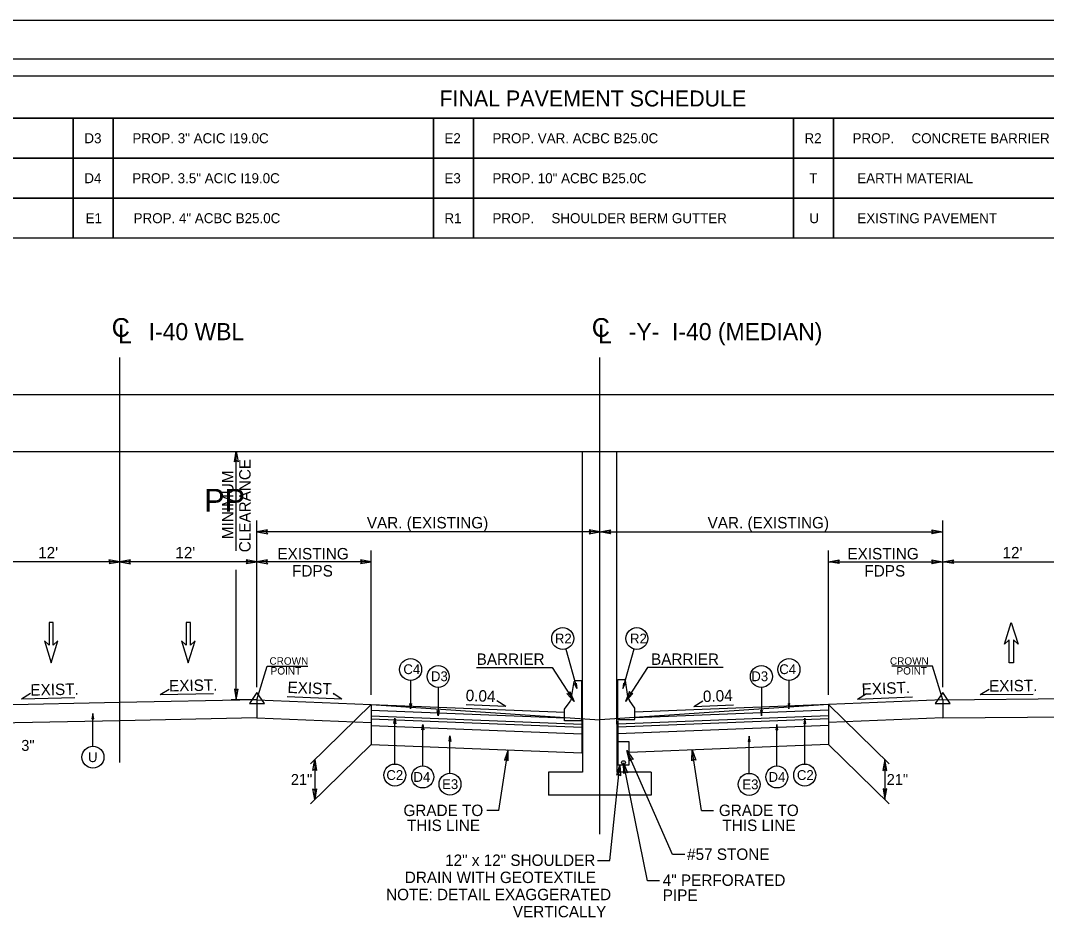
# Model space of a CAD drawing. Extents: x 1553884 to 1554215, y 810431 to 810779.
# Drawn here: x 1553971.2 to 1554061, y 810517.4 to 810596 of the extents above; entities that cross this region are included whole.
import ezdxf

# ---------------------------------------------------------------- set-up
doc = ezdxf.new("R2010")
doc.units = 0
for name, color, linetype in [('Old_Level_15', 7, 'Continuous'), ('Old_Level_2', 7, 'Continuous'), ('Old_Level_20', 7, 'Continuous'), ('P_RDY_Bridge_Abutment', 7, 'Continuous'), ('Prop Dimension', 7, 'Continuous'), ('Prop Hatching', 7, 'Continuous'), ('Prop Lane Arrow CELL', 7, 'Continuous'), ('Prop Shade Light', 7, 'Continuous'), ('Sheet Sticker Exception Certification CELL', 7, 'Continuous'), ('Typical Arrow Superelevation CELL', 7, 'Continuous'), ('Typical Detail Pavement Repair CELL', 7, 'Continuous'), ('Typical Median Barrier CELL', 7, 'Continuous'), ('Typical Shoulder Slope CELL', 7, 'Continuous'), ('Typical Text Centerline CELL', 7, 'Continuous'), ('Typical Text ID Circle CELL', 7, 'Continuous')]:
    doc.layers.add(name, color=color, linetype=linetype)

msp = doc.modelspace()

# ---------------------------------------------------------------- linework, layer by layer
at = {"layer": 'Old_Level_15'}
for points in [[(1553989.916, 810557.319), (1553990.078, 810558.257), (1553990.244, 810557.314), (1553990.078, 810557.434)], [(1553992.825, 810551.347), (1553991.887, 810551.186), (1553992.83, 810551.019), (1553992.71, 810551.186)], [(1554020.95, 810551.024), (1554021.887, 810551.186), (1554020.945, 810551.352), (1554021.064, 810551.186)], [(1554022.825, 810551.024), (1554021.887, 810551.186), (1554022.83, 810551.352), (1554022.71, 810551.186)], [(1554050.95, 810551.347), (1554051.887, 810551.186), (1554050.945, 810551.019), (1554051.064, 810551.186)], [(1553978.95, 810548.4), (1553979.887, 810548.561), (1553978.945, 810548.728), (1553979.064, 810548.561)], [(1553980.825, 810548.722), (1553979.887, 810548.561), (1553980.83, 810548.394), (1553980.71, 810548.561)], [(1553990.95, 810548.4), (1553991.887, 810548.561), (1553990.945, 810548.728), (1553991.064, 810548.561)], [(1553992.825, 810548.722), (1553991.887, 810548.561), (1553992.83, 810548.394), (1553992.71, 810548.561)], [(1554000.95, 810548.4), (1554001.887, 810548.561), (1554000.945, 810548.728), (1554001.064, 810548.561)], [(1554042.825, 810548.4), (1554041.887, 810548.561), (1554042.83, 810548.728), (1554042.71, 810548.561)], [(1554050.95, 810548.722), (1554051.887, 810548.561), (1554050.945, 810548.394), (1554051.064, 810548.561)], [(1554052.825, 810548.4), (1554051.887, 810548.561), (1554052.83, 810548.728), (1554052.71, 810548.561)], [(1553989.916, 810537.411), (1553990.078, 810536.474), (1553990.244, 810537.416), (1553990.078, 810537.296)], [(1554019.278, 810537.197), (1554019.654, 810536.323), (1554019, 810537.022), (1554019.205, 810537.013)], [(1554019.829, 810537.949), (1554019.878, 810537.476), (1554019.67, 810537.907), (1554019.766, 810537.872)], [(1554023.946, 810537.949), (1554023.897, 810537.476), (1554024.105, 810537.907), (1554024.008, 810537.872)], [(1554024.497, 810537.197), (1554024.121, 810536.323), (1554024.774, 810537.022), (1554024.569, 810537.013)], [(1553977.623, 810534.818), (1553977.542, 810535.287), (1553977.459, 810534.815), (1553977.542, 810534.875)], [(1554005.417, 810536.156), (1554005.336, 810535.688), (1554005.253, 810536.159), (1554005.336, 810536.099)], [(1554007.829, 810535.539), (1554007.748, 810535.07), (1554007.665, 810535.541), (1554007.748, 810535.481)], [(1554035.946, 810535.539), (1554036.027, 810535.07), (1554036.11, 810535.541), (1554036.027, 810535.481)], [(1554038.358, 810536.156), (1554038.439, 810535.688), (1554038.522, 810536.159), (1554038.439, 810536.099)], [(1554003.876, 810534.391), (1554003.957, 810534.86), (1554004.04, 810534.389), (1554003.957, 810534.449)], [(1554039.898, 810534.391), (1554039.817, 810534.86), (1554039.734, 810534.389), (1554039.817, 810534.449)], [(1554006.317, 810533.856), (1554006.397, 810534.325), (1554006.481, 810533.853), (1554006.397, 810533.913)], [(1554037.458, 810533.856), (1554037.377, 810534.325), (1554037.294, 810533.853), (1554037.377, 810533.913)], [(1554008.7, 810532.846), (1554008.781, 810533.315), (1554008.864, 810532.843), (1554008.781, 810532.903)], [(1554035.038, 810532.827), (1554034.957, 810533.296), (1554034.874, 810532.825), (1554034.957, 810532.885)], [(1554013.876, 810531.144), (1554013.857, 810532.095), (1554013.551, 810531.188), (1554013.733, 810531.281)], [(1554024.491, 810531.127), (1554024.255, 810532.048), (1554024.793, 810531.256), (1554024.592, 810531.297)], [(1554029.951, 810531.146), (1554029.969, 810532.097), (1554030.276, 810531.19), (1554030.093, 810531.284)], [(1553996.787, 810530.304), (1553996.948, 810531.242), (1553997.115, 810530.299), (1553996.948, 810530.419)], [(1554023.988, 810530.022), (1554023.961, 810530.973), (1554024.311, 810530.082), (1554024.124, 810530.166)], [(1554046.988, 810530.304), (1554046.826, 810531.242), (1554046.659, 810530.299), (1554046.826, 810530.419)], [(1554023.376, 810529.869), (1554023.641, 810530.782), (1554023.702, 810529.827), (1554023.549, 810529.965)], [(1553997.11, 810528.679), (1553996.948, 810527.742), (1553996.782, 810528.684), (1553996.948, 810528.564)], [(1554046.665, 810528.679), (1554046.826, 810527.742), (1554046.993, 810528.684), (1554046.826, 810528.564)]]:
    msp.add_lwpolyline(points, close=True, dxfattribs=at)
at = {"layer": 'Old_Level_2'}
msp.add_line((1554154.325, 810592.576), (1553906.825, 810592.576), dxfattribs=at)
at = {"layer": 'Old_Level_20'}
for p, q in [((1553979.887, 810536.234), (1553967.887, 810535.994)), ((1553991.887, 810536.474), (1553979.887, 810536.234)), ((1553991.887, 810536.474), (1554001.887, 810536.074)), ((1553991.887, 810536.474), (1553991.887, 810534.889)), ((1554051.887, 810536.474), (1554041.887, 810536.074)), ((1554051.887, 810536.474), (1554063.887, 810536.594)), ((1554051.887, 810536.474), (1554051.887, 810534.889)), ((1554001.887, 810536.074), (1553996.57, 810530.871)), ((1554001.887, 810536.074), (1554001.887, 810534.489)), ((1554001.887, 810536.074), (1554021.887, 810534.722)), ((1554041.887, 810536.074), (1554021.887, 810534.722)), ((1554041.887, 810536.074), (1554041.887, 810534.489)), ((1554041.887, 810536.074), (1554047.205, 810530.871)), ((1553979.887, 810534.649), (1553967.887, 810534.409)), ((1553991.887, 810534.889), (1553979.887, 810534.649)), ((1553991.887, 810534.889), (1554001.887, 810534.489)), ((1554051.887, 810534.889), (1554041.887, 810534.489)), ((1554051.887, 810534.889), (1554063.887, 810535.009)), ((1554001.887, 810532.574), (1553996.57, 810527.371)), ((1554041.887, 810532.574), (1554047.205, 810527.371)), ((1553996.948, 810531.242), (1553996.948, 810527.742)), ((1554046.826, 810531.242), (1554046.826, 810527.742))]:
    msp.add_line(p, q, dxfattribs=at)
at = {"layer": 'P_RDY_Bridge_Abutment'}
for p, q in [((1553919.386, 810563.217), (1554123.308, 810563.217)), ((1553919.386, 810558.217), (1554123.308, 810558.217)), ((1554020.387, 810534.823), (1554020.387, 810558.217)), ((1554023.387, 810534.344), (1554023.387, 810558.217)), ((1554020.387, 810534.823), (1554020.387, 810530.133)), ((1554023.387, 810534.344), (1554023.387, 810530.133)), ((1554020.387, 810530.133), (1554017.387, 810530.133)), ((1554017.387, 810530.133), (1554017.387, 810528.133)), ((1554026.387, 810530.133), (1554023.387, 810530.133)), ((1554026.387, 810530.133), (1554026.387, 810528.133)), ((1554026.387, 810528.133), (1554017.387, 810528.133))]:
    msp.add_line(p, q, dxfattribs=at)
at = {"layer": 'Prop Dimension'}
for points in [[(1553912.825, 810591.115), (1554133.325, 810591.115), (1554133.325, 810587.396), (1553912.825, 810587.396)], [(1553947.825, 810587.396), (1553975.825, 810587.396), (1553975.825, 810583.896), (1553947.825, 810583.896)], [(1553975.825, 810587.396), (1553979.325, 810587.396), (1553979.325, 810583.896), (1553975.825, 810583.896)], [(1553979.325, 810587.396), (1554007.325, 810587.396), (1554007.325, 810583.896), (1553979.325, 810583.896)], [(1554007.325, 810587.396), (1554010.825, 810587.396), (1554010.825, 810583.896), (1554007.325, 810583.896)], [(1554007.325, 810587.396), (1554010.825, 810587.396), (1554010.825, 810583.896), (1554007.325, 810583.896)], [(1554010.825, 810587.396), (1554038.825, 810587.396), (1554038.825, 810583.896), (1554010.825, 810583.896)], [(1554038.825, 810587.396), (1554042.325, 810587.396), (1554042.325, 810583.896), (1554038.825, 810583.896)], [(1554038.825, 810587.396), (1554042.325, 810587.396), (1554042.325, 810583.896), (1554038.825, 810583.896)], [(1554042.325, 810587.396), (1554070.325, 810587.396), (1554070.325, 810583.896), (1554042.325, 810583.896)], [(1553947.825, 810583.896), (1553975.825, 810583.896), (1553975.825, 810580.396), (1553947.825, 810580.396)], [(1553975.825, 810583.896), (1553979.325, 810583.896), (1553979.325, 810580.396), (1553975.825, 810580.396)], [(1553979.325, 810583.896), (1554007.325, 810583.896), (1554007.325, 810580.396), (1553979.325, 810580.396)], [(1554007.325, 810583.896), (1554010.825, 810583.896), (1554010.825, 810580.396), (1554007.325, 810580.396)], [(1554010.825, 810583.896), (1554038.825, 810583.896), (1554038.825, 810580.396), (1554010.825, 810580.396)], [(1554038.825, 810583.896), (1554042.325, 810583.896), (1554042.325, 810580.396), (1554038.825, 810580.396)], [(1554042.325, 810583.896), (1554070.325, 810583.896), (1554070.325, 810580.396), (1554042.325, 810580.396)], [(1553947.825, 810580.396), (1553975.825, 810580.396), (1553975.825, 810576.896), (1553947.825, 810576.896)], [(1553975.825, 810580.396), (1553979.325, 810580.396), (1553979.325, 810576.896), (1553975.825, 810576.896)], [(1553979.325, 810580.396), (1554007.325, 810580.396), (1554007.325, 810576.896), (1553979.325, 810576.896)], [(1554007.325, 810580.396), (1554010.825, 810580.396), (1554010.825, 810576.896), (1554007.325, 810576.896)], [(1554010.825, 810580.396), (1554038.825, 810580.396), (1554038.825, 810576.896), (1554010.825, 810576.896)], [(1554038.825, 810580.396), (1554042.325, 810580.396), (1554042.325, 810576.896), (1554038.825, 810576.896)], [(1554042.325, 810580.396), (1554070.325, 810580.396), (1554070.325, 810576.896), (1554042.325, 810576.896)]]:
    msp.add_lwpolyline(points, close=True, dxfattribs=at)
at = {"layer": 'Prop Hatching'}
for p, q in [((1553979.887, 810530.987), (1553979.887, 810566.46)), ((1554021.887, 810524.716), (1554021.887, 810566.46))]:
    msp.add_line(p, q, dxfattribs=at)
for points in [[(1553974.481, 810541.635), (1553974.075, 810541.26), (1553974.075, 810543.26), (1553973.7, 810543.26), (1553973.7, 810541.26), (1553973.294, 810541.635), (1553973.887, 810539.729)], [(1553974.481, 810541.635), (1553974.075, 810541.26), (1553974.075, 810543.26), (1553973.7, 810543.26), (1553973.7, 810541.26), (1553973.294, 810541.635), (1553973.887, 810539.729)], [(1553986.481, 810541.635), (1553986.075, 810541.26), (1553986.075, 810543.26), (1553985.7, 810543.26), (1553985.7, 810541.26), (1553985.294, 810541.635), (1553985.887, 810539.729)], [(1553986.481, 810541.635), (1553986.075, 810541.26), (1553986.075, 810543.26), (1553985.7, 810543.26), (1553985.7, 810541.26), (1553985.294, 810541.635), (1553985.887, 810539.729)], [(1554058.481, 810541.354), (1554058.075, 810541.729), (1554058.075, 810539.729), (1554057.7, 810539.729), (1554057.7, 810541.729), (1554057.294, 810541.354), (1554057.887, 810543.26)]]:
    msp.add_lwpolyline(points, close=True, dxfattribs=at)
at = {"layer": 'Prop Lane Arrow CELL'}
msp.add_line((1554156.35, 810595.951), (1553901.353, 810595.951), dxfattribs=at)
at = {"layer": 'Prop Shade Light'}
for p, q in [((1554001.887, 810536.074), (1554018.812, 810535.397)), ((1554001.887, 810535.574), (1554018.812, 810534.897)), ((1554041.887, 810536.074), (1554024.962, 810535.397)), ((1554041.887, 810535.574), (1554024.962, 810534.897)), ((1554001.887, 810535.074), (1554020.312, 810534.337)), ((1554001.887, 810534.824), (1554020.312, 810534.087)), ((1554001.887, 810534.489), (1554001.887, 810532.574)), ((1554020.312, 810534.647), (1554020.312, 810531.837)), ((1554041.887, 810535.074), (1554023.462, 810534.337)), ((1554041.887, 810534.824), (1554023.462, 810534.087)), ((1554023.462, 810534.647), (1554023.462, 810532.799)), ((1554041.887, 810534.489), (1554041.887, 810532.574)), ((1554001.887, 810534.24), (1554020.312, 810533.503)), ((1554041.887, 810534.24), (1554023.462, 810533.503)), ((1554001.887, 810532.574), (1554020.312, 810531.837)), ((1554041.887, 810532.574), (1554024.462, 810531.877))]:
    msp.add_line(p, q, dxfattribs=at)
msp.add_lwpolyline([(1554023.462, 810530.799), (1554024.462, 810530.799), (1554024.462, 810532.799), (1554023.462, 810532.799)], close=True, dxfattribs=at)
msp.add_circle((1554023.962, 810530.981), 0.167, dxfattribs=at)
at = {"layer": 'Sheet Sticker Exception Certification CELL'}
for points in [[(1553991.887, 810536.474), (1553992.791, 810539.427), (1553996.329, 810539.427)], [(1554051.887, 810536.474), (1554050.984, 810539.427), (1554047.446, 810539.427)], [(1553991.887, 810537.126), (1553991.235, 810536.148), (1553992.539, 810536.148), (1553991.887, 810537.126)], [(1554051.887, 810537.126), (1554051.235, 810536.148), (1554052.539, 810536.148), (1554051.887, 810537.126)]]:
    msp.add_lwpolyline(points, dxfattribs=at)
at = {"layer": 'Typical Arrow Superelevation CELL'}
for p, q in [((1553983.421, 810536.938), (1553984.204, 810537.411)), ((1554055.154, 810536.938), (1554055.941, 810537.403)), ((1553971.29, 810536.576), (1553972.073, 810537.049)), ((1553971.29, 810536.576), (1553975.95, 810536.669)), ((1553983.421, 810536.938), (1553988.081, 810537.031)), ((1553999.328, 810536.541), (1553994.544, 810536.733)), ((1553999.328, 810536.541), (1553998.555, 810537.03)), ((1554013.653, 810535.897), (1554012.88, 810536.386)), ((1554030.122, 810535.897), (1554030.895, 810536.386)), ((1554044.446, 810536.541), (1554045.22, 810537.03)), ((1554044.446, 810536.541), (1554049.231, 810536.733)), ((1554055.154, 810536.938), (1554059.815, 810536.984)), ((1554013.653, 810535.897), (1554010.203, 810536.035)), ((1554030.122, 810535.897), (1554033.572, 810536.035)), ((1554013.052, 810526.795), (1554013.857, 810532.095)), ((1554028.258, 810522.951), (1554024.255, 810532.048)), ((1554030.774, 810526.797), (1554029.969, 810532.097)), ((1554026.066, 810520.632), (1554023.961, 810530.973)), ((1554022.759, 810522.402), (1554023.641, 810530.782)), ((1554013.052, 810526.795), (1554011.992, 810526.795)), ((1554030.774, 810526.797), (1554031.835, 810526.797)), ((1554029.325, 810522.951), (1554028.258, 810522.951)), ((1554021.69, 810522.402), (1554022.759, 810522.402)), ((1554027.117, 810520.632), (1554026.066, 810520.632))]:
    msp.add_line(p, q, dxfattribs=at)
at = {"layer": 'Typical Median Barrier CELL'}
for points in [[(1554019.425, 810536.674), (1554019.635, 810538.076)], [(1554020.312, 810534.647), (1554020.312, 810538.147), (1554019.717, 810538.147)], [(1554023.462, 810534.751), (1554023.462, 810538.251), (1554024.057, 810538.251)], [(1554024.35, 810536.778), (1554024.14, 810538.18)], [(1554020.312, 810534.647), (1554018.812, 810534.647), (1554018.812, 810535.397), (1554018.812, 810535.647), (1554019.283, 810536.32)], [(1554023.462, 810534.751), (1554024.962, 810534.751), (1554024.962, 810535.501), (1554024.962, 810535.751), (1554024.491, 810536.424)]]:
    msp.add_lwpolyline(points, dxfattribs=at)
for centre, radius, start, end in [((1554019.717, 810538.063), 0.0833, 90, 171.46923), ((1554024.057, 810538.168), 0.0833, 8.53077, 90), ((1554018.601, 810536.797), 0.833, 325.00798, 351.46923), ((1554025.174, 810536.902), 0.833, 188.53077, 214.99202)]:
    msp.add_arc(centre, radius, start, end, dxfattribs=at)
at = {"layer": 'Typical Shoulder Slope CELL'}
for p, q in [((1553990.078, 810549.525), (1553990.078, 810558.257)), ((1553991.887, 810537.584), (1553991.887, 810552.186)), ((1554051.887, 810537.584), (1554051.887, 810552.186)), ((1554021.887, 810551.186), (1553991.887, 810551.186)), ((1554021.887, 810551.186), (1554051.887, 810551.186)), ((1554001.887, 810536.906), (1554001.887, 810549.561)), ((1554041.887, 810536.906), (1554041.887, 810549.561)), ((1553979.887, 810548.561), (1553967.887, 810548.561)), ((1553991.887, 810548.561), (1553979.887, 810548.561)), ((1553990.078, 810536.474), (1553990.078, 810547.848)), ((1554001.887, 810548.561), (1553991.887, 810548.561)), ((1554041.887, 810548.561), (1554051.887, 810548.561)), ((1554051.887, 810548.561), (1554063.887, 810548.561)), ((1553991.887, 810536.474), (1553989.624, 810536.474))]:
    msp.add_line(p, q, dxfattribs=at)
for points in [[(1554011.097, 810539.318), (1554017.706, 810539.318), (1554019.654, 810536.323)], [(1554032.677, 810539.318), (1554026.068, 810539.318), (1554024.121, 810536.323)]]:
    msp.add_lwpolyline(points, dxfattribs=at)
at = {"layer": 'Typical Text ID Circle CELL'}
for p, q in [((1554018.908, 810540.919), (1554019.878, 810537.476)), ((1554024.866, 810540.919), (1554023.897, 810537.476)), ((1554005.336, 810538.173), (1554005.336, 810535.688)), ((1554038.439, 810538.173), (1554038.439, 810535.688)), ((1554007.748, 810537.555), (1554007.748, 810535.07)), ((1554036.027, 810537.555), (1554036.027, 810535.07)), ((1553977.542, 810532.419), (1553977.542, 810535.287)), ((1554003.957, 810530.852), (1554003.957, 810534.86)), ((1554039.817, 810530.852), (1554039.817, 810534.86)), ((1554006.397, 810530.685), (1554006.397, 810534.325)), ((1554037.377, 810530.685), (1554037.377, 810534.325)), ((1554008.781, 810530.056), (1554008.781, 810533.315)), ((1554034.957, 810530.038), (1554034.957, 810533.296))]:
    msp.add_line(p, q, dxfattribs=at)
for centre in [(1554018.647, 810541.844), (1554025.127, 810541.844), (1554005.336, 810539.135), (1554038.439, 810539.135), (1554007.748, 810538.517), (1554036.027, 810538.517), (1553977.542, 810531.457), (1554003.957, 810529.891), (1554039.818, 810529.891), (1554006.397, 810529.724), (1554008.781, 810529.095), (1554034.957, 810529.076), (1554037.377, 810529.724)]:
    msp.add_circle(centre, 0.962, dxfattribs=at)

# ---------------------------------------------------------------- texts
at = {"layer": 'Old_Level_20'}
for s, p in [('3"', (1553971.271, 810532.009)), ('21"', (1553994.855, 810529.024)), ('21"', (1554046.985, 810529.024))]:
    msp.add_text(s, height=0.9558, dxfattribs=at).set_placement(p)
at = {"layer": 'Prop Dimension'}
for s, height, p in [('FINAL PAVEMENT SCHEDULE', 1.4, (1554007.857, 810588.425)), ('D3', 0.875, (1553976.795, 810585.208)), ('PROP. 3" ACIC I19.0C', 0.875, (1553980.995, 810585.208)), ('E2', 0.875, (1554008.295, 810585.208)), ('PROP. VAR. ACBC B25.0C', 0.875, (1554012.495, 810585.208)), ('R2', 0.875, (1554039.795, 810585.208)), ('PROP. ', 0.875, (1554043.995, 810585.208)), ('CONCRETE BARRIER', 0.875, (1554049.158, 810585.208)), ('D4', 0.875, (1553976.788, 810581.708)), ('PROP. 3.5" ACIC I19.0C', 0.875, (1553980.988, 810581.708)), ('E3', 0.875, (1554008.295, 810581.708)), ('PROP. 10" ACBC B25.0C', 0.875, (1554012.495, 810581.708)), ('T', 0.875, (1554040.21, 810581.708)), ('EARTH MATERIAL', 0.875, (1554044.41, 810581.708)), ('E1', 0.875, (1553976.9, 810578.208)), ('PROP. 4" ACBC B25.0C', 0.875, (1553981.1, 810578.208)), ('R1', 0.875, (1554008.295, 810578.208)), ('PROP. ', 0.875, (1554012.495, 810578.208)), ('SHOULDER BERM GUTTER', 0.875, (1554017.658, 810578.208)), ('U', 0.875, (1554040.221, 810578.208)), ('EXISTING PAVEMENT', 0.875, (1554044.421, 810578.208))]:
    msp.add_text(s, height=height, dxfattribs=at).set_placement(p)
at = {"layer": 'Prop Shade Light'}
for s, p in [('12" x 12" SHOULDER', (1554008.356, 810521.936)), ('DRAIN WITH GEOTEXTILE', (1554004.827, 810520.436)), ('NOTE: DETAIL EXAGGERATED', (1554003.187, 810518.936)), ('VERTICALLY', (1554014.278, 810517.436))]:
    msp.add_text(s, height=1, dxfattribs=at).set_placement(p)
at = {"layer": 'Sheet Sticker Exception Certification CELL'}
for s, p in [('CROWN', (1553992.988, 810539.55)), ('CROWN', (1554047.271, 810539.55)), ('POINT', (1553993.091, 810538.692)), ('POINT', (1554047.846, 810538.692))]:
    msp.add_text(s, height=0.6525, dxfattribs=at).set_placement(p)
at = {"layer": 'Typical Arrow Superelevation CELL'}
for s, height, p in [('I-40 WBL', 1.5, (1553982.418, 810567.965)), ('-Y-  I-40 (MEDIAN)', 1.5, (1554024.418, 810567.965)), ('PP', 2, (1553987.28, 810552.944)), ('VAR. (EXISTING)', 1, (1554001.504, 810551.486)), ('VAR. (EXISTING)', 1, (1554031.317, 810551.486)), ("12'", 1, (1553972.75, 810548.861)), ("12'", 1, (1553984.75, 810548.861)), ('EXISTING', 1, (1553993.68, 810548.772)), ('EXISTING', 1, (1554043.55, 810548.772)), ("12'", 1, (1554057.119, 810548.861)), ('FDPS', 1, (1553994.967, 810547.271)), ('FDPS', 1, (1554045.039, 810547.271)), ('BARRIER', 1, (1554011.112, 810539.538)), ('BARRIER', 1, (1554026.368, 810539.538)), ('GRADE TO ', 1, (1554004.707, 810526.301)), ('GRADE TO ', 1, (1554032.306, 810526.304)), ('THIS LINE', 1, (1554005.018, 810524.991)), ('THIS LINE', 1, (1554032.617, 810524.993)), ('#57 STONE', 1, (1554029.523, 810522.462)), ('4" PERFORATED', 1, (1554027.396, 810520.19)), ('PIPE', 1, (1554027.396, 810518.879))]:
    msp.add_text(s, height=height, dxfattribs=at).set_placement(p)
for s, rotation, p in [('CLEARANCE', 90, (1553991.337, 810549.396)), ('MINIMUM', 90, (1553989.837, 810550.54)), ('EXIST.', 1.14587, (1553984.209, 810537.204)), ('EXIST.', 357.70939, (1553994.548, 810537.086)), ('EXIST.', 2.29061, (1554044.815, 810536.909)), ('EXIST.', 0.57294, (1554055.945, 810537.196)), ('EXIST.', 1.14587, (1553972.078, 810536.843)), ('0.04', 357.70939, (1554010.14, 810536.38)), ('0.04', 2.29061, (1554030.929, 810536.272))]:
    msp.add_text(s, height=1, rotation=rotation, dxfattribs=at).set_placement(p)
at = {"layer": 'Typical Detail Pavement Repair CELL'}
for s, height, p in [('R2', 0.8608, (1554017.958, 810541.414)), ('R2', 0.8608, (1554024.53, 810541.414)), ('C4', 0.8608, (1554004.701, 810538.728)), ('D3', 0.8608, (1554007.114, 810538.11)), ('D3', 0.8608, (1554035.143, 810538.11)), ('C4', 0.8608, (1554037.589, 810538.728)), ('U', 0.861, (1553977.112, 810531.027)), ('C2', 0.8608, (1554003.214, 810529.461)), ('D4', 0.8608, (1554005.579, 810529.293)), ('D4', 0.8608, (1554036.651, 810529.293)), ('C2', 0.8608, (1554039.132, 810529.461)), ('E3', 0.8608, (1554008.092, 810528.664)), ('E3', 0.8608, (1554034.361, 810528.646))]:
    msp.add_text(s, height=height, dxfattribs=at).set_placement(p)
at = {"layer": 'Typical Text Centerline CELL'}
for p in [(1553979.185, 810568.256), (1554021.185, 810568.256)]:
    msp.add_text('C', height=1.64, dxfattribs=at).set_placement(p)
for p in [(1553979.73, 810567.696), (1554021.73, 810567.696)]:
    msp.add_text('L', height=1.641, rotation=359.9469, dxfattribs=at).set_placement(p)

doc.saveas('drawing.dxf')
